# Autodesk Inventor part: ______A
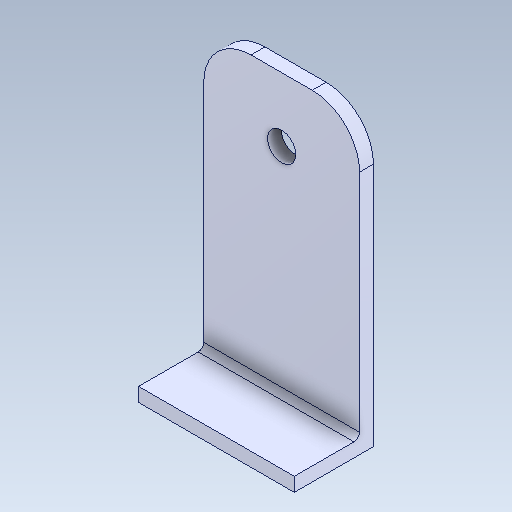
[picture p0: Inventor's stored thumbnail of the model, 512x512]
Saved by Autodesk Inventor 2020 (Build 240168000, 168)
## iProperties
Created: 2017-09
Part Number: ______A
Material: Générique
Document SubType Name: Modeling
Designer: bruno
Density: 1 g/cm^3
Appearance: Par défaut
Author: bruno
Sending System: SolidWorks 2016
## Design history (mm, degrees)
feature "Importée1"
node "Solide1"
